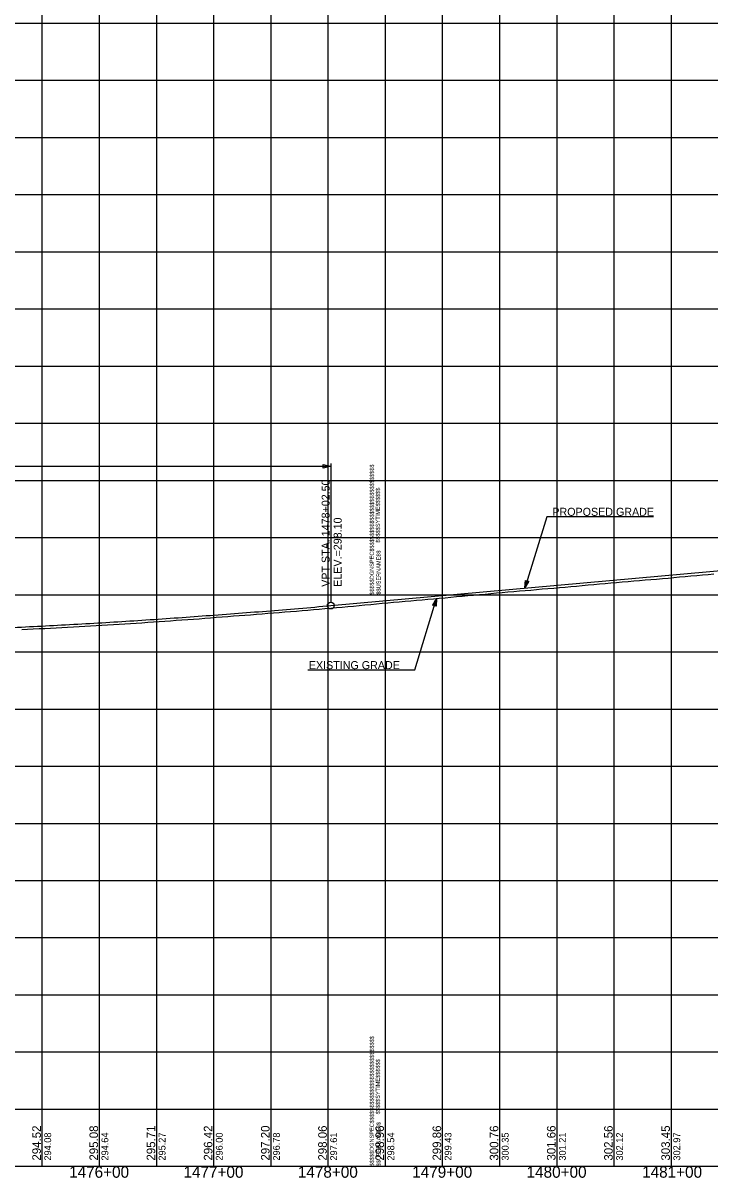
# Model space of a CAD drawing. Extents: x -90830 to 2015517, y -20856 to 836331.
# Drawn here: x 36457 to 37057, y -19397 to -18387 of the extents above; entities that cross this region are included whole.
import ezdxf

# ---------------------------------------------------------------- set-up
doc = ezdxf.new("R2010")
doc.units = 0
for name, color, linetype in [('Level 1', 7, 'Continuous'), ('RD_DDB_Profile_Elev', 7, 'Continuous'), ('RD_DDB_Profile_EX', 7, 'Continuous'), ('RD_DDB_Profile_PR', 7, 'Continuous'), ('RD_DDB_StaTX', 7, 'Continuous'), ('RD_DDB_StripGrade', 7, 'Continuous'), ('RD_DDB_VCLbl', 7, 'Continuous'), ('RD_GPK_Profile_Cell', 7, 'Continuous'), ('RD_PD_Final_TX', 7, 'Continuous'), ('RD_TX_Drainage', 7, 'Continuous')]:
    doc.layers.add(name, color=color, linetype=linetype)

msp = doc.modelspace()

# ---------------------------------------------------------------- linework, layer by layer
at = {"layer": 'Level 1'}
for p, q in [((36473.5, -17886.5), (36473.5, -18386.5)), ((36523.5, -17886.5), (36523.5, -18386.5)), ((36573.5, -17886.5), (36573.5, -18386.5)), ((36623.5, -17886.5), (36623.5, -18386.5)), ((36673.5, -17886.5), (36673.5, -18386.5)), ((36723.5, -17886.5), (36723.5, -18386.5)), ((36773.5, -17886.5), (36773.5, -18386.5)), ((36773.5, -17886.5), (36773.5, -18386.5)), ((36773.5, -17886.5), (36773.5, -18386.5)), ((36823.5, -17886.5), (36823.5, -18386.5)), ((36873.5, -17886.5), (36873.5, -18386.5)), ((36923.5, -17886.5), (36923.5, -18386.5)), ((36973.5, -17886.5), (36973.5, -18386.5)), ((37023.5, -17886.5), (37023.5, -18386.5)), ((35173.5, -18386.5), (36773.5, -18386.5)), ((35173.5, -18386.5), (36773.5, -18386.5)), ((36473.5, -18386.5), (36473.5, -18886.5)), ((36523.5, -18386.5), (36523.5, -18886.5)), ((36573.5, -18386.5), (36573.5, -18886.5)), ((36623.5, -18386.5), (36623.5, -18886.5)), ((36673.5, -18386.5), (36673.5, -18886.5)), ((36723.5, -18386.5), (36723.5, -18886.5)), ((36773.5, -18386.5), (36773.5, -18886.5)), ((36773.5, -18386.5), (36773.5, -18886.5)), ((36773.5, -18386.5), (38373.5, -18386.5)), ((36773.5, -18386.5), (36773.5, -18886.5)), ((36773.5, -18386.5), (38373.5, -18386.5)), ((36823.5, -18386.5), (36823.5, -18886.5)), ((36873.5, -18386.5), (36873.5, -18886.5)), ((36923.5, -18386.5), (36923.5, -18886.5)), ((36973.5, -18386.5), (36973.5, -18886.5)), ((37023.5, -18386.5), (37023.5, -18886.5)), ((35173.5, -18436.5), (36773.5, -18436.5)), ((36773.5, -18436.5), (38373.5, -18436.5)), ((35173.5, -18486.5), (36773.5, -18486.5)), ((36773.5, -18486.5), (38373.5, -18486.5)), ((35173.5, -18536.5), (36773.5, -18536.5)), ((36773.5, -18536.5), (38373.5, -18536.5)), ((35173.5, -18586.5), (36773.5, -18586.5)), ((36773.5, -18586.5), (38373.5, -18586.5)), ((35173.5, -18636.5), (36773.5, -18636.5)), ((36773.5, -18636.5), (38373.5, -18636.5)), ((35173.5, -18686.5), (36773.5, -18686.5)), ((36773.5, -18686.5), (38373.5, -18686.5)), ((35173.5, -18736.5), (36773.5, -18736.5)), ((36773.5, -18736.5), (38373.5, -18736.5)), ((35173.5, -18786.5), (36773.5, -18786.5)), ((36773.5, -18786.5), (38373.5, -18786.5)), ((35173.5, -18836.5), (36773.5, -18836.5)), ((36773.5, -18836.5), (38373.5, -18836.5)), ((35173.5, -18886.5), (36773.5, -18886.5)), ((35173.5, -18886.5), (36773.5, -18886.5)), ((36473.5, -18886.5), (36473.5, -19386.5)), ((36523.5, -18886.5), (36523.5, -19386.5)), ((36573.5, -18886.5), (36573.5, -19386.5)), ((36623.5, -18886.5), (36623.5, -19386.5)), ((36673.5, -18886.5), (36673.5, -19386.5)), ((36723.5, -18886.5), (36723.5, -19386.5)), ((36773.5, -18886.5), (36773.5, -19386.5)), ((36773.5, -18886.5), (36773.5, -19386.5)), ((36773.5, -18886.5), (38373.5, -18886.5)), ((36773.5, -18886.5), (38373.5, -18886.5)), ((36773.5, -18886.5), (36773.5, -19386.5)), ((36823.5, -18886.5), (36823.5, -19386.5)), ((36873.5, -18886.5), (36873.5, -19386.5)), ((36923.5, -18886.5), (36923.5, -19386.5)), ((36973.5, -18886.5), (36973.5, -19386.5)), ((37023.5, -18886.5), (37023.5, -19386.5)), ((35173.5, -18936.5), (36773.5, -18936.5)), ((36773.5, -18936.5), (38373.5, -18936.5)), ((35173.5, -18986.5), (36773.5, -18986.5)), ((36773.5, -18986.5), (38373.5, -18986.5)), ((35173.5, -19036.5), (36773.5, -19036.5)), ((36773.5, -19036.5), (38373.5, -19036.5)), ((35173.5, -19086.5), (36773.5, -19086.5)), ((36773.5, -19086.5), (38373.5, -19086.5)), ((35173.5, -19136.5), (36773.5, -19136.5)), ((36773.5, -19136.5), (38373.5, -19136.5)), ((35173.5, -19186.5), (36773.5, -19186.5)), ((36773.5, -19186.5), (38373.5, -19186.5)), ((35173.5, -19236.5), (36773.5, -19236.5)), ((36773.5, -19236.5), (38373.5, -19236.5)), ((35173.5, -19286.5), (36773.5, -19286.5)), ((36773.5, -19286.5), (38373.5, -19286.5)), ((35173.5, -19336.5), (36773.5, -19336.5)), ((36773.5, -19336.5), (38373.5, -19336.5)), ((35173.5, -19386.5), (36773.5, -19386.5)), ((36773.5, -19386.5), (38373.5, -19386.5))]:
    msp.add_line(p, q, dxfattribs=at)
at = {"layer": 'RD_DDB_Profile_EX'}
for points in [[(36920.9, -18880.7), (36925.9, -18880.2), (36930.9, -18879.8), (36935.9, -18879.3), (36940.9, -18878.9), (36945.9, -18878.4), (36950.9, -18877.9), (36955.9, -18877.5), (36960.9, -18877), (36965.9, -18876.6), (36970.9, -18876.1), (36975.9, -18875.7), (36980.9, -18875.3), (36985.9, -18874.9), (36990.9, -18874.5), (36995.9, -18874), (37000.9, -18873.6), (37005.9, -18873.2), (37010.9, -18872.8), (37015.9, -18872.3), (37020.9, -18871.9), (37025.9, -18871.5), (37030.9, -18871), (37035.9, -18870.6), (37040.9, -18870.1), (37045.9, -18869.7), (37050.9, -18869.2), (37055.9, -18868.8), (37060.9, -18868.3)], [(36455.9, -18917), (36460.9, -18916.7), (36465.9, -18916.5), (36470.9, -18916.2), (36475.9, -18916), (36480.9, -18915.7), (36485.9, -18915.4), (36490.9, -18915.2), (36495.9, -18914.9), (36500.9, -18914.6), (36505.9, -18914.3), (36510.9, -18914), (36515.9, -18913.7), (36520.9, -18913.5), (36525.9, -18913.2), (36530.9, -18912.9), (36535.9, -18912.6), (36540.9, -18912.2), (36545.9, -18911.9), (36550.9, -18911.6), (36555.9, -18911.3), (36560.9, -18911), (36565.9, -18910.6), (36570.9, -18910.3), (36575.9, -18910), (36580.9, -18909.6), (36585.9, -18909.3), (36590.9, -18908.9), (36595.9, -18908.6), (36600.9, -18908.2), (36605.9, -18907.8), (36610.9, -18907.5), (36615.9, -18907.1), (36620.9, -18906.7), (36625.9, -18906.3), (36630.9, -18905.9), (36635.9, -18905.5), (36640.9, -18905.1), (36645.9, -18904.7), (36650.9, -18904.4), (36655.9, -18904), (36660.9, -18903.6), (36665.9, -18903.2), (36670.9, -18902.8), (36675.9, -18902.4), (36680.9, -18902), (36685.9, -18901.6), (36690.9, -18901.2), (36695.9, -18900.8), (36700.9, -18900.4), (36705.9, -18899.9), (36710.9, -18899.5), (36715.9, -18899.1), (36720.9, -18898.7), (36725.9, -18898.2), (36730.9, -18897.8), (36735.9, -18897.3), (36740.9, -18896.8), (36745.9, -18896.4), (36750.9, -18895.9), (36755.9, -18895.4), (36760.9, -18895), (36765.9, -18894.5), (36770.9, -18894), (36775.9, -18893.6), (36780.9, -18893.1), (36785.9, -18892.7), (36790.9, -18892.3), (36795.9, -18891.8), (36800.9, -18891.4), (36805.9, -18890.9), (36810.9, -18890.5), (36815.9, -18890.1), (36820.9, -18889.6), (36825.9, -18889.2), (36830.9, -18888.7), (36835.9, -18888.2), (36840.9, -18887.8), (36845.9, -18887.3), (36850.9, -18886.8), (36855.9, -18886.4), (36860.9, -18885.9), (36865.9, -18885.4), (36870.9, -18885), (36875.9, -18884.5), (36880.9, -18884.1), (36885.9, -18883.7), (36890.9, -18883.2), (36895.9, -18882.8), (36900.9, -18882.4), (36905.9, -18882), (36910.9, -18881.5), (36915.9, -18881.1), (36920.9, -18880.7)]]:
    msp.add_lwpolyline(points, dxfattribs=at)
at = {"layer": 'RD_DDB_Profile_PR'}
msp.add_line((36726, -18896), (39423.5, -18653.4), dxfattribs=at)
msp.add_spline([(35321, -18874.1), (35349.1, -18877.4), (35377.2, -18880.7), (35405.3, -18883.8), (35433.4, -18886.8), (35461.5, -18889.6), (35489.6, -18892.4), (35517.7, -18895), (35545.8, -18897.5), (35573.9, -18899.9), (35602, -18902.2), (35630.1, -18904.3), (35658.2, -18906.4), (35686.3, -18908.3), (35714.4, -18910.1), (35742.5, -18911.8), (35770.6, -18913.4), (35798.7, -18914.8), (35826.8, -18916.1), (35854.9, -18917.3), (35883, -18918.4), (35911.1, -18919.4), (35939.2, -18920.2), (35967.3, -18921), (35995.4, -18921.6), (36023.5, -18922.1), (36051.6, -18922.5), (36079.7, -18922.7), (36107.8, -18922.9), (36135.9, -18922.9), (36164, -18922.8), (36192.1, -18922.6), (36220.2, -18922.3), (36248.3, -18921.8), (36276.4, -18921.2), (36304.5, -18920.5), (36332.6, -18919.7), (36360.7, -18918.8), (36388.8, -18917.8), (36416.9, -18916.6), (36445, -18915.3), (36473.1, -18913.9), (36501.2, -18912.4), (36529.3, -18910.8), (36557.4, -18909), (36585.5, -18907.1), (36613.6, -18905.1), (36641.7, -18903), (36669.8, -18900.8), (36697.9, -18898.5), (36726, -18896)], degree=3, dxfattribs=at)
at = {"layer": 'RD_DDB_VCLbl'}
for p, q in [((35321, -18774.1), (36726, -18774.1)), ((36726, -18771.6), (36726, -18893))]:
    msp.add_line(p, q, dxfattribs=at)
msp.add_circle((36726, -18896), 3, dxfattribs=at)
at = {"layer": 'RD_GPK_Profile_Cell'}
msp.add_line((4823.5, -19386.5), (75223.5, -19386.5), dxfattribs=at)
at = {"layer": 'RD_PD_Final_TX'}
for p, q in [((36895.7, -18880.7), (36896.1, -18874)), ((36897.6, -18874.5), (36895.7, -18880.7)), ((36895.7, -18880.7), (36899.2, -18875)), ((36896.1, -18874), (36899.2, -18875)), ((36818.4, -18889.8), (36815, -18895.6)), ((36818.1, -18896.5), (36815, -18895.6)), ((36816.6, -18896), (36818.4, -18889.8)), ((36818.4, -18889.8), (36818.1, -18896.5))]:
    msp.add_line(p, q, dxfattribs=at)
for points in [[(37008.2, -18818.3), (36914.8, -18818.3), (36895.7, -18880.7)], [(36897.5, -18874.6), (36895.8, -18880.4), (36897.5, -18874.5), (36895.8, -18880.1), (36897.4, -18874.5), (36895.8, -18879.9), (36897.4, -18874.5), (36895.8, -18879.6), (36897.3, -18874.5), (36895.8, -18879.3), (36897.2, -18874.5), (36895.9, -18878.9), (36897.1, -18874.5), (36895.9, -18878.6), (36897.1, -18874.4), (36895.9, -18878.3), (36897, -18874.4), (36895.9, -18878), (36897, -18874.4), (36895.9, -18877.7), (36896.9, -18874.4), (36896, -18877.4), (36896.8, -18874.3), (36896, -18876.9), (36896.7, -18874.3), (36896, -18876.6), (36896.6, -18874.3), (36896, -18876.2), (36896.5, -18874.3), (36896, -18875.8), (36896.5, -18874.2), (36896.1, -18875.5), (36896.4, -18874.2), (36896.1, -18875.2), (36896.3, -18874.2), (36896.1, -18874.9), (36896.3, -18874.2), (36896.1, -18874.5), (36896.2, -18874.2)], [(36895.9, -18880.3), (36897.6, -18874.6), (36896, -18880.1), (36897.7, -18874.6), (36896.1, -18880), (36897.8, -18874.6), (36896.2, -18879.8), (36897.8, -18874.7), (36896.3, -18879.6), (36897.9, -18874.7), (36896.5, -18879.4), (36897.9, -18874.7), (36896.6, -18879.2), (36898, -18874.7), (36896.7, -18878.9), (36898.1, -18874.7), (36896.9, -18878.7), (36898.2, -18874.7), (36897, -18878.4), (36898.2, -18874.7), (36897.2, -18878.2), (36898.3, -18874.8), (36897.3, -18877.9), (36898.3, -18874.8), (36897.5, -18877.6), (36898.4, -18874.8), (36897.7, -18877.4), (36898.4, -18874.8), (36897.9, -18877.1), (36898.5, -18874.8), (36898, -18876.8), (36898.6, -18874.9), (36898.2, -18876.5), (36898.6, -18874.9), (36898.3, -18876.3), (36898.7, -18875), (36898.5, -18876), (36898.8, -18874.9), (36898.6, -18875.8), (36898.9, -18875), (36898.7, -18875.6), (36899, -18875.1), (36899.1, -18875), (36899, -18875.1)], [(36706, -18952.2), (36799.4, -18952.2), (36818.4, -18889.8)], [(36818.3, -18890.2), (36816.5, -18895.9), (36818.2, -18890.4), (36816.5, -18895.9), (36818.1, -18890.6), (36816.4, -18895.9), (36818, -18890.7), (36816.4, -18895.9), (36817.8, -18890.9), (36816.3, -18895.9), (36817.7, -18891.1), (36816.2, -18895.9), (36817.6, -18891.4), (36816.2, -18895.9), (36817.4, -18891.6), (36816.1, -18895.8), (36817.3, -18891.9), (36816, -18895.8), (36817.2, -18892.1), (36816, -18895.8), (36817, -18892.4), (36815.9, -18895.8), (36816.8, -18892.6), (36815.9, -18895.7), (36816.6, -18893), (36815.8, -18895.7), (36816.5, -18893.2), (36815.7, -18895.7), (36816.3, -18893.5), (36815.7, -18895.7), (36816.2, -18893.8), (36815.6, -18895.7), (36816, -18894), (36815.5, -18895.6), (36815.8, -18894.2), (36815.5, -18895.6), (36815.7, -18894.6), (36815.4, -18895.6), (36815.6, -18894.8), (36815.3, -18895.6), (36815.4, -18894.9), (36815.2, -18895.5), (36815.1, -18895.5), (36815.2, -18895.5)], [(36816.6, -18896), (36818.4, -18890.2), (36816.7, -18896), (36818.4, -18890.5), (36816.7, -18896), (36818.4, -18890.7), (36816.8, -18896), (36818.4, -18890.9), (36816.9, -18896), (36818.3, -18891.3), (36817, -18896.1), (36818.3, -18891.6), (36817, -18896.1), (36818.3, -18891.9), (36817.1, -18896.1), (36818.3, -18892.3), (36817.2, -18896.1), (36818.2, -18892.6), (36817.2, -18896.2), (36818.2, -18892.8), (36817.3, -18896.2), (36818.2, -18893.2), (36817.4, -18896.2), (36818.2, -18893.6), (36817.5, -18896.2), (36818.2, -18893.9), (36817.5, -18896.3), (36818.2, -18894.4), (36817.6, -18896.3), (36818.1, -18894.7), (36817.7, -18896.3), (36818.1, -18895), (36817.8, -18896.3), (36818.1, -18895.3), (36817.8, -18896.4), (36818.1, -18895.7), (36817.9, -18896.4), (36818.1, -18896.1), (36818, -18896.4)]]:
    msp.add_lwpolyline(points, dxfattribs=at)
at = {"layer": 'RD_TX_Drainage'}
msp.add_lwpolyline([(36719.4, -18772.5), (36726, -18774.1), (36719.4, -18775.8)], close=True, dxfattribs=at)

# ---------------------------------------------------------------- texts
at = {"layer": 'Level 1'}
for s, p in [('$$$$$DGNSPEC$$$$$$$$$$$$$$$$$$$$$$$$$$$$', (36763.6, -18886.6)), ('$$$$$SYTIME$$$$$$', (36768.9, -18841)), ('$$USERNAME$$', (36769.5, -18886.4)), ('$$$$$DGNSPEC$$$$$$$$$$$$$$$$$$$$$$$$$$$$', (36763.6, -19386.6)), ('$$$$$SYTIME$$$$$$', (36768.9, -19341)), ('$$USERNAME$$', (36769.5, -19386.4))]:
    msp.add_text(s, height=3.544, rotation=90, dxfattribs=at).set_placement(p)
at = {"layer": 'RD_DDB_Profile_Elev'}
for s, p in [('294.52', (36472.5, -19381.5)), ('295.08', (36522.5, -19381.5)), ('295.71', (36572.5, -19381.5)), ('296.42', (36622.5, -19381.5)), ('297.20', (36672.5, -19381.5)), ('298.06', (36722.5, -19381.5)), ('298.96', (36772.5, -19381.5)), ('299.86', (36822.5, -19381.5)), ('300.76', (36872.5, -19381.5)), ('301.66', (36922.5, -19381.5)), ('302.56', (36972.5, -19381.5)), ('303.45', (37022.5, -19381.5))]:
    msp.add_text(s, height=7.5, rotation=90, dxfattribs=at).set_placement(p)
at = {"layer": 'RD_DDB_StaTX'}
for s, p in [('1476+00', (36497.2, -19396.5)), ('1477+00', (36597.2, -19396.5)), ('1478+00', (36697.2, -19396.5)), ('1479+00', (36797.2, -19396.5)), ('1480+00', (36897.2, -19396.5)), ('1481+00', (36998.2, -19396.5))]:
    msp.add_text(s, height=10, dxfattribs=at).set_placement(p)
at = {"layer": 'RD_DDB_StripGrade'}
for s, height, p in [('VPT STA. 1478+02.50 ', 7, (36725, -18879.6)), ('ELEV.=298.10', 7, (36735.5, -18879.6)), ('294.08', 6, (36481.5, -19381.5)), ('294.64', 6, (36531.5, -19381.5)), ('295.27', 6, (36581.5, -19381.5)), ('296.00', 6, (36631.5, -19381.5)), ('296.78', 6, (36681.5, -19381.5)), ('297.61', 6, (36731.5, -19381.5)), ('298.54', 6, (36781.5, -19381.5)), ('299.43', 6, (36831.5, -19381.5)), ('300.35', 6, (36881.5, -19381.5)), ('301.21', 6, (36931.5, -19381.5)), ('302.12', 6, (36981.5, -19381.5)), ('302.97', 6, (37031.5, -19381.5))]:
    msp.add_text(s, height=height, rotation=90, dxfattribs=at).set_placement(p)
at = {"layer": 'RD_PD_Final_TX'}
for s, p in [('PROPOSED GRADE', (36919.7, -18817.5)), ('EXISTING GRADE', (36706.8, -18951.6))]:
    msp.add_text(s, height=7, dxfattribs=at).set_placement(p)

doc.saveas('drawing.dxf')
